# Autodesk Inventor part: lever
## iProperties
Author: E. MOSS
Created: 2001-10
Part Number: lever
Document SubType Name: Modeling
Designer: E. MOSS
Control State: 0
Master: False
Checked Out: False
PropertySet Name: Design Tracking Control
Shininess: 64.0
Angle Display Precision: 2
Document Length Units: 11272
Document Angle Units: 11286
Document Time Units: 11279
Document Mass Units: 11290
Document Length Units Precision: 3
Document Angle Units Precision: 2
Compacted: False
PropertySet Name: _Private Model Information
Density: 0.0
Volumn: 0.0
Area: 0.0
PropertySet Name: Model Information
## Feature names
1. Extrusion1
2. Fillet1
